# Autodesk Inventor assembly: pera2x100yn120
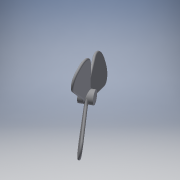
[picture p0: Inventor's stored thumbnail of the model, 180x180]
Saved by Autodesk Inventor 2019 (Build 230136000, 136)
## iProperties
Created: 2020-08
Part Number: pera2x100yn120
Material: 一般
Document SubType Name: Assembly
Designer: kikut
Author: kikut
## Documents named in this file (2)
- F:\openFOAM\bathrobo\bathrobo05\oversetmeshpera2\CAD\pera2x100yn120.iam
- F:\openFOAM\bathrobo\bathrobo05\oversetmeshpera2\CAD\pera02.ipt
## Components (1 placed, 1 different names)
1. pera02:1 — 角度:1, メイト:1, メイト:2, メイト:3
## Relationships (4: Mate 3, Angle 1)
- 角度:1 [Angle]: pera02:1
- メイト:1 [Mate]: pera02:1
- メイト:2 [Mate]: pera02:1
- メイト:3 [Mate]: pera02:1
